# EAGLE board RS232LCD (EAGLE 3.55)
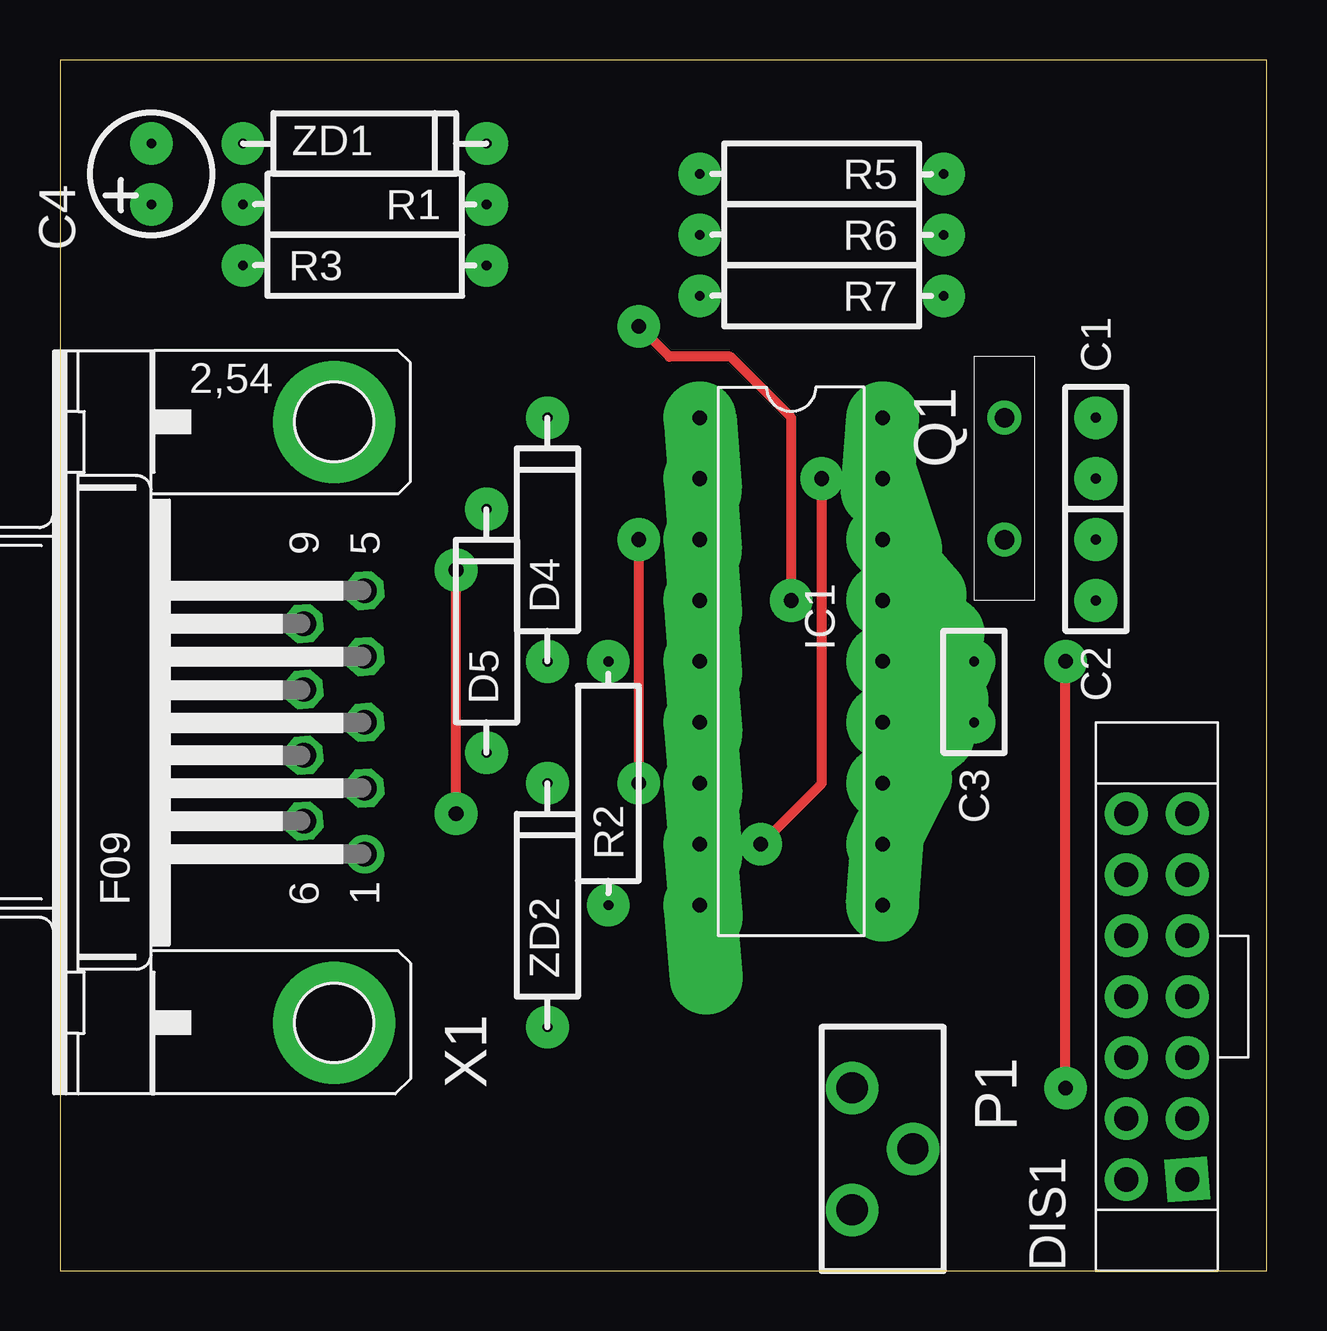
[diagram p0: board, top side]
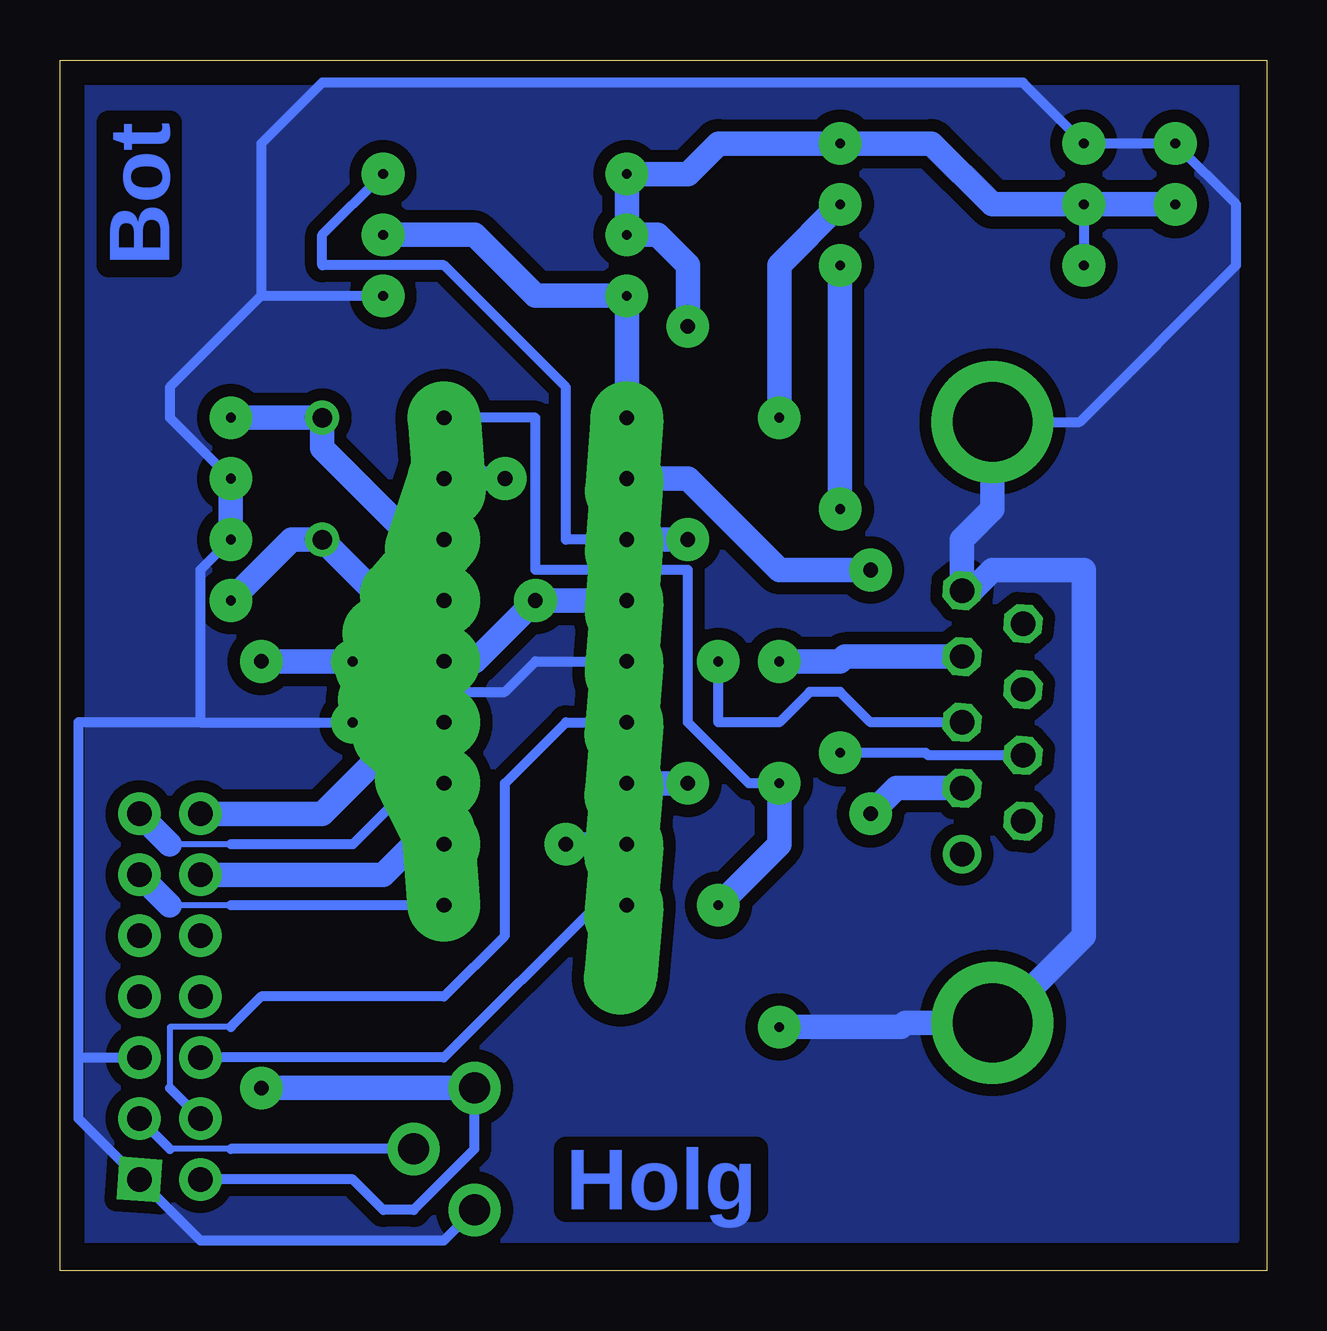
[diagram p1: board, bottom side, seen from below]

Size 50.3 x 50.47 mm. Coordinates in mm from the lower left corner, seen from the top.
Outline: 0,0 50.3,0 50.3,50.47 0,50.47 0,0
Copper layers used: Top, Bottom

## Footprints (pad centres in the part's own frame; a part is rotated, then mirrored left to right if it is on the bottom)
RM2,5 = drill 0.406 pad 1.778 round:  0,0;  2.54,0
KO01 = drill 0.406 pad 1.778 round:  0,0;  2.54,0
O04 = drill 0.406 pad 1.778 round:  0,0;  10.16,0
7 = drill 1.016 pad 1.778 square:  0,0 | drill 1.016 pad 1.778 round:  0,2.54;  2.54,0;  2.54,2.54;  5.08,0;  5.08,2.54;  7.62,0;  7.62,2.54;  10.16,0;  10.16,2.54;  12.7,0;  12.7,2.54;  15.24,0;  15.24,2.54
L-18B = drill 0.61 pad 3.048 offset:  0,0;  2.54,0;  15.24,0;  17.78,0;  5.08,0;  7.62,0;  12.7,0;  10.16,0;  20.32,0;  20.32,7.62;  17.78,7.62;  15.24,7.62;  12.7,7.62;  10.16,7.62;  7.62,7.62;  5.08,7.62;  2.54,7.62;  0,7.62
IM_STE = drill 1.295 pad 2.184 round:  0,0;  5.08,0;  2.54,2.54
ARZ_ST = drill 0.813 pad 1.422 round:  0,0;  5.08,0
S04 = drill 0.406 pad 1.778 round:  0,0;  10.16,0
9HP = drill 1.016 pad 1.6 round:  -5.486,-1.27 | drill 1.016 pad 1.6 octagon:  -2.743,-1.27;  0,-1.27;  2.743,-1.27;  5.486,-1.27;  -4.115,1.27;  -1.372,1.27;  1.372,1.27;  4.115,1.27 | drill 3.302 pad 5.08 round:  -12.522,0;  12.522,0

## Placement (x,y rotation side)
C1  27p  [RM2,5]  43.18,33.02 90 top
C2  27p  [RM2,5]  43.18,30.48 270 top
C3  C100NK  [RM2,5]  38.1,25.4 270 top
C4  47u  [KO01]  3.81,44.45 90 top
D4  1N4148  [O04]  20.32,25.4 90 top
D5  1N4148  [O04]  17.78,21.59 90 top
DIS1  2X7  [7]  46.99,3.81 90 top
IC1  16F628-04  [L-18B]  26.67,35.56 270 top
P1  22k  [IM_STE]  33.02,7.62 270 top
Q1  2.4576MHz  [ARZ_ST]  39.37,35.56 270 top
R1  1k  [S04]  17.78,44.45 180 top
R2  47k  [S04]  22.86,15.24 90 top
R3  1k  [S04]  7.62,41.91 0 top
R5  47k  [S04]  36.83,45.72 180 top
R6  47k  [S04]  36.83,43.18 180 top
R7  47k  [S04]  36.83,40.64 180 top
X1  F09HP  [9HP]  11.43,22.86 90 top
ZD1  5V1  [O04]  7.62,46.99 0 top
ZD2  5V1  [O04]  20.32,10.16 90 top

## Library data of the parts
C1-C4 D4 D5 R1-R3 R5-R7 ZD1 ZD2 = holg_plt
DIS1 = LCD1
IC1 = PIC
P1 = holgnorm
Q1 = bts
X1 = SUBD-A

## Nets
+5V: C3. C4. DIS1. IC1. P1. R1. R3. R5. R6. ZD1.
GND: C1. C2. C3. C4. DIS1. IC1. P1. R7. X1. ZD1. ZD2.
N$1: C1. IC1. Q1.
N$2: C2. IC1. Q1.
N$3: D4. X1.
N$4: D5. X1.
N$5: D4. R1.
N$6: IC1.
N$7: DIS1. IC1.
N$8: R2. X1.
N$9: DIS1. IC1.
N$10: DIS1. IC1.
N$11: DIS1. IC1.
N$12: DIS1. IC1.
N$13: DIS1. IC1.
N$14: D5. R3.
N$15: IC1. R2. ZD2.
N$16: IC1. R5.
N$17: IC1. X1.
N$18: IC1. R6. R7.
N$19: DIS1. P1.

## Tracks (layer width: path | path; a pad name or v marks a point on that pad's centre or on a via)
+5V  (via drill 0.61 pad 1.78)
  Top 0.406: v41.91,7.62 v41.91,25.4 | v30.48,27.94 30.48,35.56 27.94,38.1 25.4,38.1 v24.13,39.37
  Bottom 0.406: R1. 7.62,41.91 | 44.45,3.81 38.1,3.81 36.83,2.54 35.56,2.54 33.02,5.08 33.02,7.62
  Bottom 1.016: 3.81,44.45 R1. 11.43,44.45 13.97,46.99 ZD1. 22.86,46.99 24.13,45.72 R5. R6. 25.4,43.18 24.13,41.91 v24.13,39.37 | 33.02,7.62 v41.91,7.62 | v41.91,25.4 38.1,25.4 34.29,25.4 33.02,25.4 v30.48,27.94 26.67,27.94
GND
  Bottom 0.406: 43.18,30.48 44.45,29.21 44.45,22.86 | 44.45,22.86 C3. 36.83,24.13 31.75,24.13 30.48,25.4 26.67,25.4 | 12.29,28.35 12.7,28.35 | 11.43,10.34 11.25,10.34 | 15.06,10.34 15.24,10.16 | 33.02,2.54 34.29,1.27 44.45,1.27 46.99,3.81 49.53,6.35 49.53,8.89 | 41.91,40.64 41.91,46.99 39.37,49.53 10.16,49.53 7.62,46.99 C4. 1.27,44.45 1.27,41.91 7.8,35.38 X1. | 43.18,33.02 45.72,35.56 45.72,36.83 41.91,40.64 | 41.91,40.64 36.83,40.64 | 49.53,8.89 46.99,8.89 | 49.53,8.89 49.53,22.86 44.45,22.86
  Bottom 1.016: 43.18,33.02 43.18,30.48 | X1. 11.43,31.75 12.7,30.48 12.7,28.35 | 12.29,28.35 11.43,29.21 7.62,29.21 7.62,13.97 11.25,10.34 | 11.43,10.34 15.06,10.34 | 15.24,10.16 20.32,10.16
  pour Bottom (isolate 0.508): 1.27,1.27 49.53,1.27 49.53,49.53 1.27,49.53
N$1
  Bottom 1.016: 34.29,30.48 35.56,30.48 39.37,34.29 39.37,35.56 C1.
N$2
  Bottom 1.016: 34.29,27.94 36.83,27.94 Q1. 40.64,30.48 C2.
N$3
  Bottom 1.016: 12.7,25.6 17.58,25.6 17.78,25.4 20.32,25.4
N$4
  Bottom 0.406: 10.16,21.49 14.12,21.49 14.22,21.59 17.78,21.59
N$5
  Bottom 1.016: D4. 20.32,41.91 17.78,44.45
N$6  (via drill 0.61 pad 1.78)
  Top 0.406: v31.75,33.02 31.75,20.32 v29.21,17.78
  Bottom 1.016: v31.75,33.02 34.29,33.02 | 26.67,17.78 v29.21,17.78
N$7
  Bottom 1.016: 34.29,22.86 35.56,22.86 39.37,19.05 DIS1.
N$8
  Bottom 0.406: 12.7,22.86 16.51,22.86 17.78,24.13 19.05,24.13 20.32,22.86 22.86,22.86 R2.
N$9
  Bottom 0.254: 43.18,17.78 45.72,17.78
  Bottom 0.406: 34.29,20.32 35.56,20.32 38.1,17.78 43.18,17.78
  Bottom 1.016: 45.72,17.78 46.99,19.05
N$10
  Bottom 1.016: 34.29,17.78 35.56,17.78 36.83,16.51 44.45,16.51
N$11
  Bottom 0.254: 43.18,15.24 45.72,15.24
  Bottom 0.406: 34.29,15.24 43.18,15.24
  Bottom 1.016: 45.72,15.24 46.99,16.51
N$12
  Bottom 0.406: 44.45,8.89 34.29,8.89 27.94,15.24 26.67,15.24
N$13
  Bottom 0.254: 45.72,7.62 45.72,10.16 43.18,10.16
  Bottom 0.406: 26.67,22.86 29.21,22.86 31.75,20.32 31.75,13.97 34.29,11.43 41.91,11.43 43.18,10.16 | 45.72,7.62 44.45,6.35
N$14
  Bottom 1.016: D5. R3.
N$15
  Bottom 0.406: ZD2. 21.59,20.32 24.13,22.86 24.13,29.21 30.48,29.21 30.48,35.56 IC1.
  Bottom 1.016: ZD2. 20.32,17.78 22.86,15.24
N$16  (via drill 0.61 pad 1.78)
  Top 0.406: v24.13,20.32 v24.13,30.48
  Bottom 0.406: 36.83,45.72 39.37,43.18 39.37,41.91 34.29,41.91 29.21,36.83 29.21,30.48 26.67,30.48
  Bottom 1.016: v24.13,20.32 26.67,20.32 | v24.13,30.48 26.67,30.48
N$17  (via drill 0.61 pad 1.78)
  Top 0.406: v16.51,19.05 v16.51,29.21
  Bottom 1.016: 26.67,33.02 24.13,33.02 20.32,29.21 v16.51,29.21 | 12.7,20.12 15.44,20.12 v16.51,19.05
N$18
  Bottom 1.016: 36.83,43.18 33.02,43.18 30.48,40.64 R7. 26.67,35.56
N$19
  Bottom 0.254: 43.18,5.08 45.72,5.08
  Bottom 0.406: 45.72,5.08 46.99,6.35 | P1. 43.18,5.08

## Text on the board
Bottom: Bot | Holg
